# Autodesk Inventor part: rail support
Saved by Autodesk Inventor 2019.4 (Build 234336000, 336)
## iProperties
Created: 2020-09
Part Number: rail support
Material: Generic
Document SubType Name: Modeling
Designer: Administrator
Density: 1 g/cm^3
Appearance: Default
Title: rail support
Author: Administrator
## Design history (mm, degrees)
feature "Body1"
body "Solid1"
